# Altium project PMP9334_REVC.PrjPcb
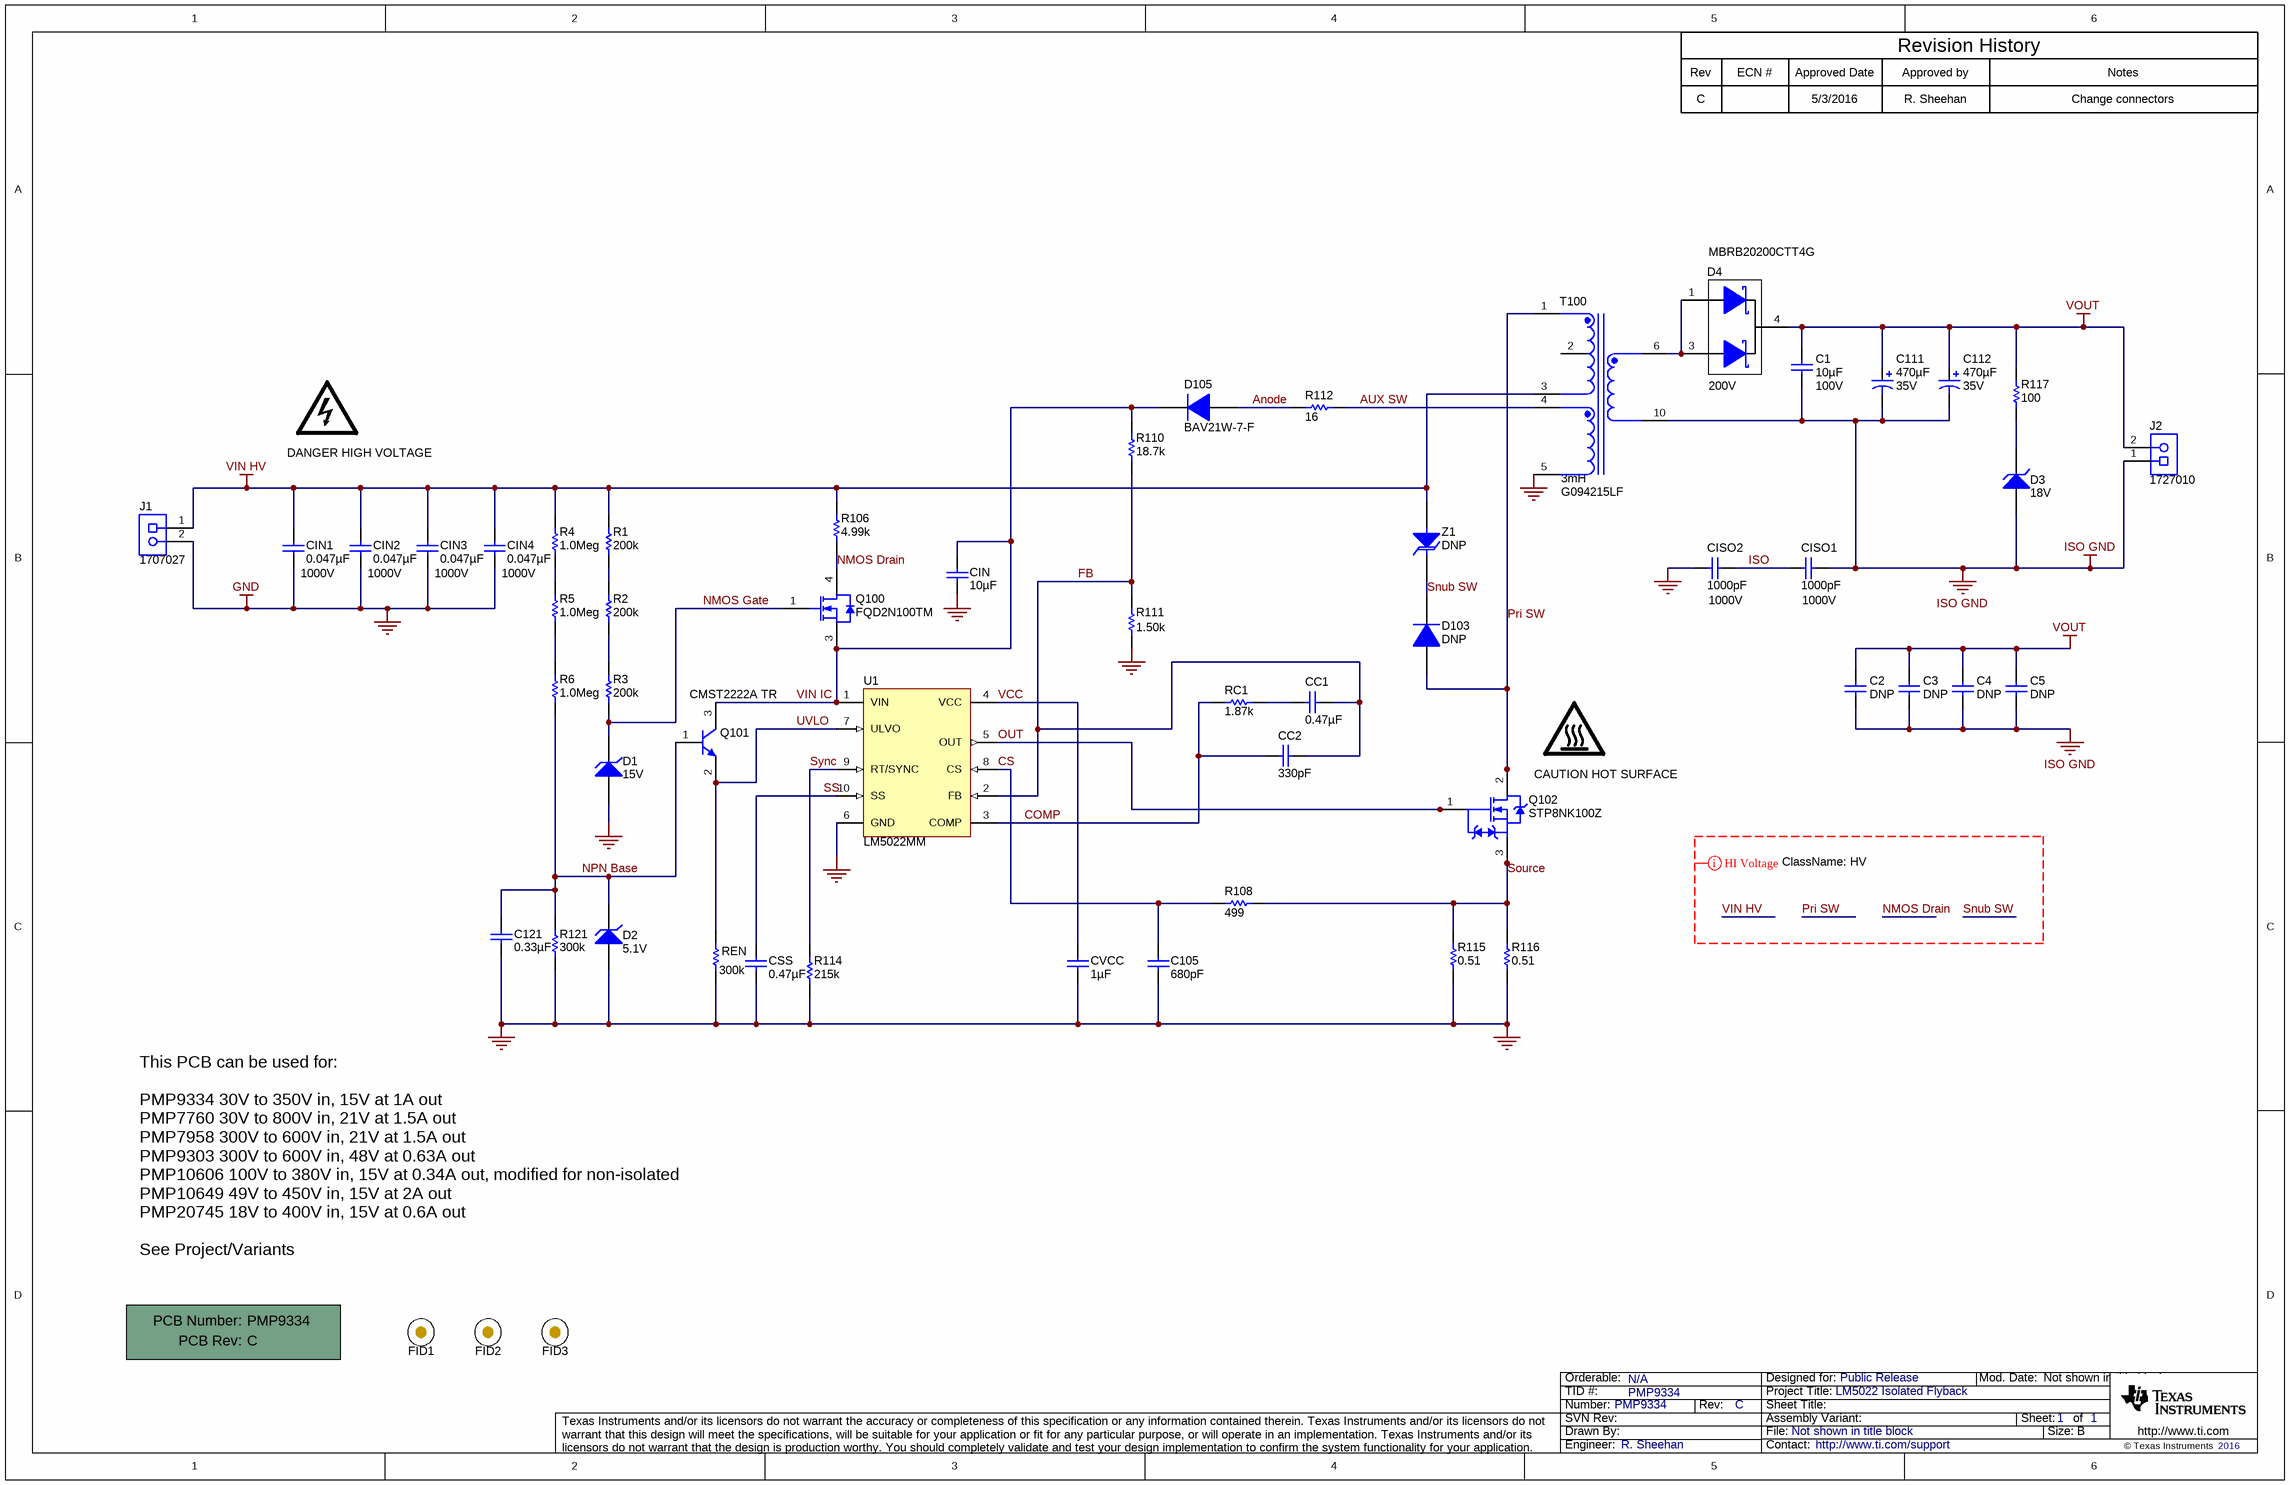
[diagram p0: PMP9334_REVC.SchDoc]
CopyrightYear: 2016; EVM_Orderable: N/A; PCB_Layout: R. Sheehan; PCB_Rev: C; PRJ_Customer: Public Release; PRJ_Engineer: R. Sheehan; PRJ_Number: PMP9334; PRJ_Title: LM5022 Isolated Flyback; SCH_Rev: C; TechSupport: http://www.ti.com/support; TID: PMP9334
1 sheet, 58 parts. Net scope: global (net labels, ports and power ports of the same name join across sheets).
Board file: PMP9334_REVC.PcbDoc

## Sheet PMP9334_REVC.SchDoc
size 431 x 279 mm; Date: Not shown in title block; ApprovedBy: Not shown in title block; CheckedBy: Not shown in title block; Author: Not shown in title block; CompanyName: Not shown in title block; Engineer: Not shown in title block; Organization: Not shown in title block; Address1: Not shown in title block; Address2: Not shown in title block; Address3: Not shown in title block; Address4: Not shown in title block; DocumentNumber: 1; Revision: Use project parameter SCH_Rev; SheetNumber: 1; SheetTotal: 1; PageSetup: Record=PageOptions¦CenterHorizontal=True¦CenterVertical=True¦PrintScale=1.00¦XCorrection=1.00¦YCorrection=1.00¦PrintKind=0¦BorderSize=5000000¦LeftOffset=0¦BottomOffset=0¦Orientation=2¦PaperLength=1000¦PaperWidth=1000¦Scale=100¦PaperSource=15¦PrintQuality=600¦MediaType=1¦DitherType=10¦PaperKind=Letter¦PrintScaleMode=1

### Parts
!PCB  Printed Circuit Board  (value not drawn)  (mechanical)
C1  ValueDisplayed: 10µF  Value2: 100V  [2220_280]  (hidden comment: C5750X7S2A106M230KB)
C2  DNP  [2220_280]
C3  DNP  [2220_280]
C4  DNP  [2220_280]
C5  DNP  [2220_280]
C105  ValueDisplayed: 680pF  [0603L]  (hidden comment: C0603C681K5RACTU)
C111  Value2: 35V  ValueDisplayed: 470µF  [CAPSMT_62_KE0]  (hidden comment: EMVY350ATR471MKE0S)
C112  Value2: 35V  ValueDisplayed: 470µF  [CAPSMT_62_KE0]  (hidden comment: EMVY350ATR471MKE0S)
C121  ValueDisplayed: 0.33µF  [0805_HV]  (hidden comment: GRM21BR71E334KA01L)
CC1  ValueDisplayed: 0.47µF  [0603L]  (hidden comment: C0603C474K4RACTU)
CC2  ValueDisplayed: 330pF  [0603L]  (hidden comment: C0603C331K5RACTU)
CIN  ValueDisplayed: 10µF  [0805_HV]  (hidden comment: C2012X5R1E106K125AB)
CIN1  ValueDisplayed: 0.047µF  Value2: 1000V  [1812]  (hidden comment: C1812V473KDRACTU)
CIN2  ValueDisplayed: 0.047µF  Value2: 1000V  [1812]  (hidden comment: C1812V473KDRACTU)
CIN3  ValueDisplayed: 0.047µF  Value2: 1000V  [1812]  (hidden comment: C1812V473KDRACTU)
CIN4  ValueDisplayed: 0.047µF  Value2: 1000V  [1812]  (hidden comment: C1812V473KDRACTU)
CISO1  ValueDisplayed: 1000pF  Value2: 1000V  [1210]  (hidden comment: VJ1210A102JXGAT5Z)
CISO2  ValueDisplayed: 1000pF  Value2: 1000V  [1210]  (hidden comment: VJ1210A102JXGAT5Z)
CSS  ValueDisplayed: 0.47µF  [0603L]  (hidden comment: C0603C474K4RACTU)
CVCC  ValueDisplayed: 1µF  [0603L]  (hidden comment: GRM188R61E105KA12D)
D1  value 15V  [SMA]  (hidden comment: CMZ5929B TR13)
D2  value 5.1V  [SOD-123]  (hidden comment: MMSZ5231B-7-F)
D3  value 18V  [SMA]  (hidden comment: CMZ5931B LEAD FREE)
D4  MBRB20200CTT4G  value 200V  [DDPAK]
D103  DNP  [SMA]
D105  BAV21W-7-F  [SOD-123]
FID1  Fiducial  [Fiducial10-20]  (value not drawn)
FID2  Fiducial  [Fiducial10-20]  (value not drawn)
FID3  Fiducial  [Fiducial10-20]  (value not drawn)
J1  1707027  [Phoenix_1707027]
J2  1727010  [PhoenixConact_1727010]
Logo1  DANGER HIGH VOLTAGE  [IEC_HighVoltage_Small]  (no BOM)
Logo2  CAUTION HOT SURFACE  [IEC_HotSurface_Small]  (no BOM)
Q100  FQD2N100TM  [DPAK]
Q101  CMST2222A TR  [SOT-323]
Q102  STP8NK100Z  [TO220-3_A]
R1  value 200k  [0805_HV]  (hidden comment: CRCW0805200KJNEA)
R2  value 200k  [0805_HV]  (hidden comment: CRCW0805200KJNEA)
R3  value 200k  [0805_HV]  (hidden comment: CRCW0805200KJNEA)
R4  value 1.0Meg  [0805_HV]  (hidden comment: CRCW08051M00JNEA)
R5  value 1.0Meg  [0805_HV]  (hidden comment: CRCW08051M00JNEA)
R6  value 1.0Meg  [0805_HV]  (hidden comment: CRCW08051M00JNEA)
R106  value 4.99k  [1206]  (hidden comment: CRCW12064K99FKEA)
R108  ValueDisplayed: 499  [0603L]  (hidden comment: CRCW0603499RFKEA)
R110  value 18.7k  [0603L]  (hidden comment: RG1608P-1872-B-T5)
R111  value 1.50k  [0603L]  (hidden comment: CRCW06031K50FKEA)
R112  value 16  [0603L]  (hidden comment: CRCW060316R0JNEA)
R114  ValueDisplayed: 215k  [0603L]  (hidden comment: CRCW0603215KFKEA)
R115  ValueDisplayed: 0.51  [1210]  (hidden comment: MCR25JZHFLR510)
R116  ValueDisplayed: 0.51  [1210]  (hidden comment: MCR25JZHFLR510)
R117  value 100  [1206]  (hidden comment: CRCW1206100RFKEA)
R121  value 300k  [0603L]  (hidden comment: RC0603FR-07300KL)
RC1  ValueDisplayed: 1.87k  [0603L]  (hidden comment: CRCW06031K87FKEA)
REN  value 300k  [0603L]  (hidden comment: RC0603FR-07300KL)
T100  G094215LF  ValueDisplayed: 3mH  [GCI_G094215LF]
U1  LM5022MM  [MUB10A_N]
Z1  DNP  [SMA]

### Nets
GND: C105.2 C121.2 CIN.2 CIN1.2 CIN2.2 CIN3.2 CIN4.2 CISO2.2 CSS.2 CVCC.2 D1.2(A) D2.2(A) J1.2 R111.1 R114.1 R115.1 R116.1 R121.1 REN.1 T100.5 U1.6(GND)
ISO GND: C1.2 C2.2 C3.2 C4.2 C5.2 C111.2(-) C112.2(-) CISO1.1 D3.2(A) J2.1 T100.10
VIN HV: CIN1.1 CIN2.1 CIN3.1 CIN4.1 J1.1 R1.2 R4.2 R106.2 T100.3 Z1.2(A)
VOUT: C1.1 C2.1 C3.1 C4.1 C5.1 C111.1(+) C112.1(+) D4.4(K) J2.2 R117.2
Anode: D105.2(A) R112.2
AUX SW: R112.1 T100.4
COMP: CC2.2 RC1.1 U1.3(COMP)
CS: C105.1 R108.1 U1.8(CS)
FB: CC1.1 CC2.1 R110.1 R111.2 U1.2(FB)
ISO: CISO1.2 CISO2.1
NMOS Drain: Q100.4(D) R106.1
NMOS Gate: D1.1(K) Q100.1(G) R3.1
NPN Base: C121.1 D2.1(K) Q101.1(B) R6.1 R121.2
OUT: Q102.1(G) U1.5(OUT)
Pri SW: D103.2(A) Q102.2(D) T100.1
Snub SW: D103.1(K) Z1.1(K)
Source: Q102.3(S) R108.2 R115.2 R116.2
SS: CSS.1 U1.10(SS)
Sync: R114.2 U1.9(RT/SYNC)
UVLO: Q101.2(E) REN.2 U1.7(ULVO)
VCC: CVCC.1 U1.4(VCC)
VIN IC: CIN.1 D105.1(K) Q100.3(S) Q101.3(C) R110.2 U1.1(VIN)
NetCC1_2: CC1.2 RC1.2
NetD3_1: D3.1(K) R117.1
NetD4_1: D4.1(A) D4.3(A) T100.6
NetR1_1: R1.1 R2.2
NetR2_1: R2.1 R3.2
NetR4_1: R4.1 R5.2
NetR5_1: R5.1 R6.2

Not connected (* = marked no-connect by the designer): T100 2

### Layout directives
net class HV: NMOS Drain, Pri SW, Snub SW, VIN HV

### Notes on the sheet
- Rev
- C
- ECN #
- Approved Date
- 5/3/2016
- Approved by
- R. Sheehan
- Revision History
- Notes
- Change connectors
- This PCB can be used for:
  PMP9334 30V to 350V in, 15V at 1A out
  PMP7760 30V to 800V in, 21V at 1.5A out
  PMP7958 300V to 600V in, 21V at 1.5A out
  PMP9303 300V to 600V in, 48V at 0.63A out
  PMP10606 100V to 380V in, 15V at 0.34A out, modified for non-isolated
  PMP10649 49V to 450V in, 15V at 2A out
  PMP20745 18V to 400V in, 15V at 0.6A out
  See Project/Variants

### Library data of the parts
!PCB = PCB: Manufacturer: Any; PartNumber: PMP9334; SymbolCreator: a0412235
C1 = C5750X7S2A106M230KB: CAP, CERM, 10 µF, 100 V, +/- 20%, X7S, 2220; Manufacturer: TDK; Polarized: N; CompType: Capacitor; Value: 10uF; U/M: EA; Cap_F: 0.00001; Tolerance_%: 20; Value1: Unknown; VDC_V: 100; TaMin_C: -55; TaMax_C: 125; Cap_Case: 2220; AEC Category: Q200
C2-C5 = C5750X7S2A106M230KB: CAP, CERM, 10 µF, 100 V, +/- 20%, X7S, 2220; Manufacturer: TDK; Polarized: N; CompType: Capacitor; Value: 10uF; ValueDisplayed: 10µF; U/M: EA; Cap_F: 0.00001; Tolerance_%: 20; Value1: Unknown; VDC_V: 100; Value2: 100V; TaMin_C: -55; TaMax_C: 125; Cap_Case: 2220; AEC Category: Q200
C105 = C0603C681K5RACTU: CAP, CERM, 680 pF, 50 V, +/- 10%, X7R, 0603; Manufacturer: Kemet; Cap_Case: 0603; Polarized: N; TaMax_C: 125; TaMin_C: -55; Tolerance_%: 10; VDC_V: 50; Cap_F: 0.00000000068; CompType: Capacitor; Value: 680pF; Value1: Unknown; Value2: 50V; U/M: EA; AEC Category: Q200
C111 C112 = EMVY350ATR471MKE0S: CAP, AL, 470 µF, 35 V, +/- 20%, 0.07 ohm, SMD; Manufacturer: Chemi-Con; Cap_Case: KE0; ESR_ohm: 0.07; IRMS_A: 0.82; Polarized: Y; TaMax_C: 105; TaMin_C: -55; Tolerance_%: 20; VDC_V: 35; CompType: Capacitor; Cap_F: 0.00047; Value: 470uF; U/M: EA; AEC Category: Q200
C121 = GRM21BR71E334KA01L: CAP, CERM, 0.33 µF, 25 V, +/- 10%, X7R, 0805; Manufacturer: MuRata; Cap_Case: 0805; Polarized: N; TaMax_C: 125; TaMin_C: -55; Tolerance_%: 10; VDC_V: 25; Cap_F: 0.00000033; CompType: Capacitor; Value: 0.33uF; Value1: Unknown; Value2: 25V; U/M: EA; AEC Category: Q200
CC1 CSS = C0603C474K4RACTU: CAP, CERM, 0.47 µF, 16 V, +/- 10%, X7R, 0603; Manufacturer: Kemet; Cap_Case: 0603; Polarized: N; TaMax_C: 125; TaMin_C: -55; Tolerance_%: 10; VDC_V: 16; Cap_F: 0.00000047; CompType: Capacitor; Value: 0.47uF; Value1: Unknown; Value2: 16V; U/M: EA; AEC Category: Q200
CC2 = C0603C331K5RACTU: CAP, CERM, 330 pF, 50 V, +/- 10%, X7R, 0603; Manufacturer: Kemet; Cap_Case: 0603; Polarized: N; TaMax_C: 125; TaMin_C: -55; Tolerance_%: 10; VDC_V: 50; Cap_F: 0.00000000033; CompType: Capacitor; Value: 330pF; Value1: Unknown; Value2: 50V; U/M: EA; AEC Category: Q200
CIN = C2012X5R1E106K125AB: CAP, CERM, 10 µF, 25 V, +/- 10%, X5R, 0805; Manufacturer: TDK; Cap_Case: 0805; Polarized: N; TaMax_C: 85; TaMin_C: -55; Tolerance_%: 10; VDC_V: 25; Cap_F: 0.00001; CompType: Capacitor; Value: 10uF; Value1: Unknown; Value2: 25V; U/M: EA; AEC Category: Q200
CIN1-CIN4 = C1812V473KDRACTU: CAP, CERM, 0.047 µF, 1000 V, +/- 10%, X7R, 1812; Manufacturer: Kemet; Polarized: N; TaMax_C: 125; TaMin_C: -55; Tolerance_%: 10; Cap_F: 0.000000047; CompType: Capacitor; VDC_V: 1000; Value: 0.047uF; U/M: EA; Value1: Unknown; AEC Category: Q200
CISO1 CISO2 = VJ1210A102JXGAT5Z: CAP, CERM, 1000 pF, 1000 V, +/- 5%, C0G/NP0, 1210; Manufacturer: Vishay-Vitramon; Polarized: N; CompType: Capacitor; Value: 1000pF; U/M: EA; Cap_F: 0.000000001; Tolerance_%: 5; Value1: Unknown; VDC_V: 1000; TaMin_C: -55; TaMax_C: 125; AEC Category: Q200
CVCC = GRM188R61E105KA12D: CAP, CERM, 1 µF, 25 V, +/- 10%, X5R, 0603; Manufacturer: MuRata; Cap_Case: 0603; Polarized: N; TaMax_C: 85; TaMin_C: -55; Tolerance_%: 10; VDC_V: 25; Cap_F: 0.000001; CompType: Capacitor; Value: 1uF; Value1: Unknown; Value2: 25V; U/M: EA; AEC Category: Q200
D1 = CMZ5929B TR13: Diode, Zener, 15 V, 1.5 W, SMA; Manufacturer: Central Semiconductor; SymbolCreator: a0412235; U/M: EA; Power_W: 1.5; Vz_V: 15; Value1: 1.5W; RJA_CperW: 250; AEC Category: Q101
D2 = MMSZ5231B-7-F: Diode, Zener, 5.1 V, 500 mW, SOD-123; Manufacturer: Diodes Inc.; SymbolCreator: a0412235; U/M: EA; Power_W: 0.5; Vz_V: 5.1; Value1: 0.5W; RJA_CperW: 350; AEC Category: Q101
D3 = CMZ5931B LEAD FREE: Diode, Zener, 18 V, 900 mW, SMA; Manufacturer: Central Semiconductor; U/M: EA; Power_W: 0.9; Vz_V: 18; Value1: 0.9W; RJA_CperW: 139; SymbolCreator: a0412235; AEC Category: Q101
D4 = MBRB20200CTT4G: Diode, Schottky, 200 V, 20 A, DDPAK; Manufacturer: ON Semiconductor; U/M: EA; Vf_V: 1; Value1: 20A; Value2: 1V; Io_A: 20; Vr_V: 200; TJmax_C: 150; RJC_CperW: 2; AEC Category: Q101
D103 = STTH112A: Diode, Ultrafast, 1200 V, 1 A, SMA; Manufacturer: STMicroelectronics; Value: 1200V; Value1: 1A; U/M: EA; Vr_V: 1200; AEC Category: Q101; AEC Qualified: N; Vf_V: 1.9; Value2: 1.9V; Io_A: 1; TJmax_C: 175
D105 = BAV21W-7-F: Diode, Switching, 200 V, 0.2 A, SOD-123; Manufacturer: Diodes Inc.; Vf_V: 1.25; Io_A: 0.2; Vr_V: 200; TJmax_C: 150; Value: 200V; Value1: 0.2A; Value2: 1.25V; U/M: EA; AEC Category: Q101
FID1-FID3 = Fiducial: Fiducial mark.  There is nothing to buy or mount.; SymbolCreator: codlsc
J1 = 1707027: Terminal Block, 7.62mm, 2 Pos, TH; Manufacturer: Phoenix Contact; SymbolCreator: a0412235; Pitch_mm: 7.62; Gender: Female; Row_Count: 1; Current_A: 16; Voltage_V: 1000; Cert_CSA: Y
J2 = 1727010: Conn Term Block, 2POS, 3.81mm, TH; Manufacturer: Phoenix Contact; SymbolCreator: a0412235; CompType: Terminal Block
Logo1 = IEC_HighVoltage: IEC 61010-1 High Voltage Warning; SymbolCreator: a0412235
Logo2 = IEC_HotSurface: IEC 61010-1 Hot Surface Warning; SymbolCreator: a0412235
Q100 = FQD2N100TM: MOSFET, N-CH, 1000 V, 1.6 A, DPAK; Manufacturer: Fairchild Semiconductor; Alternate Manufacturer: None; U/M: EA; ChType: N; Value: 1000V; VdsMax_V: 1000; Value1: ? ohm; Value2: 12 nC; QgTyp_nC: 12; Vgs_V: 30; IdsMax_A: 1.6; AEC Category: Q101
Q101 = CMST2222A TR, Central Semiconductor: Transistor, NPN, 40 V, 0.6 A, SOT-323; CompType: BJT; PNP: 0; NPN: 1; Vceo_V: 40; Vcesat1_V: 0.3; Value: 40 V; IcRated_A: 0.6; Value1: 0.6 A; TaMin_C: -65; TaMax_C: 150; U/M: EA; AEC Category: Q101
Q102 = STP8NK100Z: MOSFET, N-CH, 1000 V, 6.5 A, TO-220AB; Manufacturer: STMicroelectronics; Alternate Manufacturer: None; SymbolCreator: x0208325; U/M: EA; ChType: N; Value: 1000V; VdsMax_V: 1000; Value1: ? ohm; Value2: 73 nC; QgTyp_nC: 73; Vgs_V: 30; IdsMax_A: 6.5; AEC Category: Q101
R1-R3 = CRCW0805200KJNEA: RES, 200 k, 5%, 0.125 W, 0805; Manufacturer: Vishay-Dale; CompType: Resistor; Res_ohm: 200000; Tolerance_%: 5; Power_W: 0.125; Value2: 0.125W; VDC_V: 150; TempCo: 200 ppm/C; EIA_Code: E24; U/M: EA; AEC Category: Q200
R4-R6 = CRCW08051M00JNEA: RES, 1.0 M, 5%, 0.125 W, 0805; Manufacturer: Vishay-Dale; CompType: Resistor; Res_ohm: 1000000; Value_Code: 1M00; Tolerance_%: 5; Power_W: 0.125; Value2: 0.125W; VDC_V: 150; TempCo: 200 ppm/C; EIA_Code: E24; U/M: EA; ValueDisplayed: 1.0M; AEC Category: Q200
R106 = CRCW12064K99FKEA: RES, 4.99 k, 1%, 0.25 W, 1206; Manufacturer: Vishay-Dale; CompType: Resistor; Res_ohm: 4990; Value_Code: 4k99; Tolerance_%: 1; Power_W: 0.25; Value2: 0.25W; VDC_V: 200; TempCo: 100 ppm/C; EIA_Code: E96; U/M: EA; AEC Category: Q200
R108 = CRCW0603499RFKEA: RES, 499, 1%, 0.1 W, 0603; Manufacturer: Vishay-Dale; CompType: Resistor; Tolerance_%: 1; VDC_V: 75; Power_W: 0.1; Value: 499; Value_Code: 499R; Value2: 0.1W; EIA_Code: E96; TempCo: 100 ppm/C; U/M: EA; AEC Category: Q200
R110 = RG1608P-1872-B-T5: RES, 18.7 k, 0.1%, 0.1 W, 0603; Manufacturer: Susumu Co Ltd; CompType: Resistor; Res_ohm: 18700; Value_Code: 18k7; Tolerance_%: 0.1; Value2: 0.1W; VDC_V: 75; TempCo: 25 ppm/C; EIA_Code: E192; U/M: EA; AEC Category: Q200
R111 = CRCW06031K50FKEA: RES, 1.50 k, 1%, 0.1 W, 0603; Manufacturer: Vishay-Dale; CompType: Resistor; Res_ohm: 1500; Value_Code: 1k50; Tolerance_%: 1; Power_W: 0.1; Value2: 0.1W; VDC_V: 75; TempCo: 100 ppm/C; EIA_Code: E96; U/M: EA; AEC Category: Q200
R112 = CRCW060316R0JNEA: RES, 16, 5%, 0.1 W, 0603; Manufacturer: Vishay-Dale; CompType: Resistor; Value_Code: 16R0; Tolerance_%: 5; Power_W: 0.1; Value2: 0.1W; VDC_V: 75; TempCo: 200 ppm/C; EIA_Code: E24; U/M: EA; AEC Category: Q200
R114 = CRCW0603215kFKEA: RES, 215 k, 1%, 0.1 W, 0603; Manufacturer: Vishay-Dale; CompType: Resistor; Tolerance_%: 1; VDC_V: 75; Power_W: 0.1; Res_ohm: 215000; Value: 215k; Value2: 0.1W; EIA_Code: E96; TempCo: 100 ppm/C; U/M: EA; AEC Category: Q200
R115 R116 = MCR25JZHFLR510: RES, 0.51, 1%, 0.5 W, 1210; Manufacturer: Rohm; CompType: Resistor; Tolerance_%: 1; Power_W: 0.5; Value: 0.51; Value_Code: R510; Value2: 0.5W; EIA_Code: E96; TempCo: 200 ppm/C; U/M: EA; AEC Category: Q200
R117 = CRCW1206100RFKEA: RES, 100, 1%, 0.25 W, 1206; Manufacturer: Vishay-Dale; CompType: Resistor; Tolerance_%: 1; VDC_V: 200; Power_W: 0.25; Value_Code: 100R; Value2: 0.25W; EIA_Code: E96; TempCo: 100 ppm/C; U/M: EA; AEC Category: Q200
R121 REN = RC0603FR-07300KL: RES, 300 k, 1%, 0.1 W, 0603; Manufacturer: Yageo America; CompType: Resistor; Res_ohm: 300000; Tolerance_%: 1; Power_W: 0.1; Value2: 0.1W; VDC_V: 150; TempCo: 200 ppm/C; U/M: EA; AEC Category: Q200
RC1 = CRCW06031K87FKEA: RES, 1.87 k, 1%, 0.1 W, 0603; Manufacturer: Vishay-Dale; CompType: Resistor; Tolerance_%: 1; VDC_V: 75; Power_W: 0.1; Res_ohm: 1870; Value: 1.87k; Value_Code: 1k87; Value2: 0.1W; EIA_Code: E96; TempCo: 100 ppm/C; U/M: EA; AEC Category: Q200
T100 = G094215LF: Transformer, 3 mH, TH; Manufacturer: GCI Technologies; SymbolCreator: Altium; Value: 3mH; Lp: 3000; DCR_ohm: 3.35; LeakageL: 50
U1 = LM5022MM: 60V Low Side Controller for Boost and SEPIC, 10-pin MSOP; Manufacturer: Texas Instruments; CompType: Switcher; PackageTopMarking: ZXTT*5022; PowerWise: Y
Z1 = SMAJ250A: Diode, TVS, Uni, 250 V, 400 W, SMA; Manufacturer: Littelfuse; Value: 250V; U/M: EA; Power_W: 400; Vr_V: 250; Value1: 400W; RJA_CperW: 120; AEC Category: Q101

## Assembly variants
PMP9334: not fitted C2 C3 C4 C5 D103 FID1 FID2 FID3 Z1
PMP7760: not fitted C2 C3 C4 C5 D103 FID1 FID2 FID3 Z1; alternate parts Q102 -> STP3N150, R115 -> CRCW12061R00FKEA, R116 -> CRCW12061R00FKEA, C105 -> GRM1885C1H101JA01D, D1 -> CMZ5931B LEAD FREE, D3 -> 1SMB5934BT3G, R1 -> CRCW08051M00JNEA, R2 -> CRCW08051M00JNEA, R3 -> CRCW08051M00JNEA, R106 -> CRCW120610K0JNEA, R108 -> CRCW06033K32FKEA, R111 -> CRCW06031K27FKEA, R112 -> CRCW06038R20JNEA, R121 -> CRCW0603205KFKEA, REN -> CRCW060320K5FKEA
PMP7958: not fitted C2 C3 C4 C5 D103 FID1 FID2 FID3 R116 Z1; alternate parts Q102 -> STP3N150, CISO1 -> GRM42A7U3F101JW31L, D1 -> CMZ5931B LEAD FREE, D3 -> 1SMB5934BT3G, R106 -> CRCW120610K0JNEA, R111 -> CRCW06031K27FKEA, R112 -> CRCW060316R0JNEA, R115 -> CRCW12061R00FKEA, R121 -> CRCW060320K5FKEA, REN -> CRCW060320K5FKEA
PMP9303: not fitted C112 D103 FID1 FID2 FID3 R116 Z1; alternate parts Q102 -> C2M1000170D, C111 -> EMVY630ATR221MKE0S, CC1 -> GRM188R71H683KA93D, CISO1 -> GRM42A7U3F101JW31L, D1 -> CMZ5931B LEAD FREE, D3 -> 1SMB5942BT3G, R106 -> CRCW120610K0JNEA, R110 -> CRCW060348R7FKEA, R111 -> CRCW06031K27FKEA, R112 -> CRCW060316R0JNEA, R115 -> CRCW12061R00FKEA, R121 -> CRCW060320K5FKEA, RC1 -> CRCW060310K0FKEA, REN -> CRCW060320K5FKEA
PMP10606: not fitted C2 C3 C4 C5 C112 D3 D103 FID1 FID2 FID3 R117 Z1; alternate parts Q102 -> STP3N150, CC1 -> GRM188R71E104KA01D, CISO1 -> CRCW12060000Z0EA, CISO2 -> CRCW12060000Z0EA, R110 -> CRCW060316K5FKEA, RC1 -> CRCW06039K53FKEA
PMP10649: not fitted C2 C3 C4 C5 D103 FID1 FID2 FID3 Z1
PMP20745: not fitted C2 C3 C4 C5 D103 FID1 FID2 FID3 Z1; alternate parts R116 -> CRCW12061R00FKEA, R108 -> CRCW06033K32FKEA, C105 -> GRM1885C1H101JA01D, R106 -> CRCW12062K49FKEA, R121 -> CRCW0603392KFKEA, REN -> CRCW060320K5FKEA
